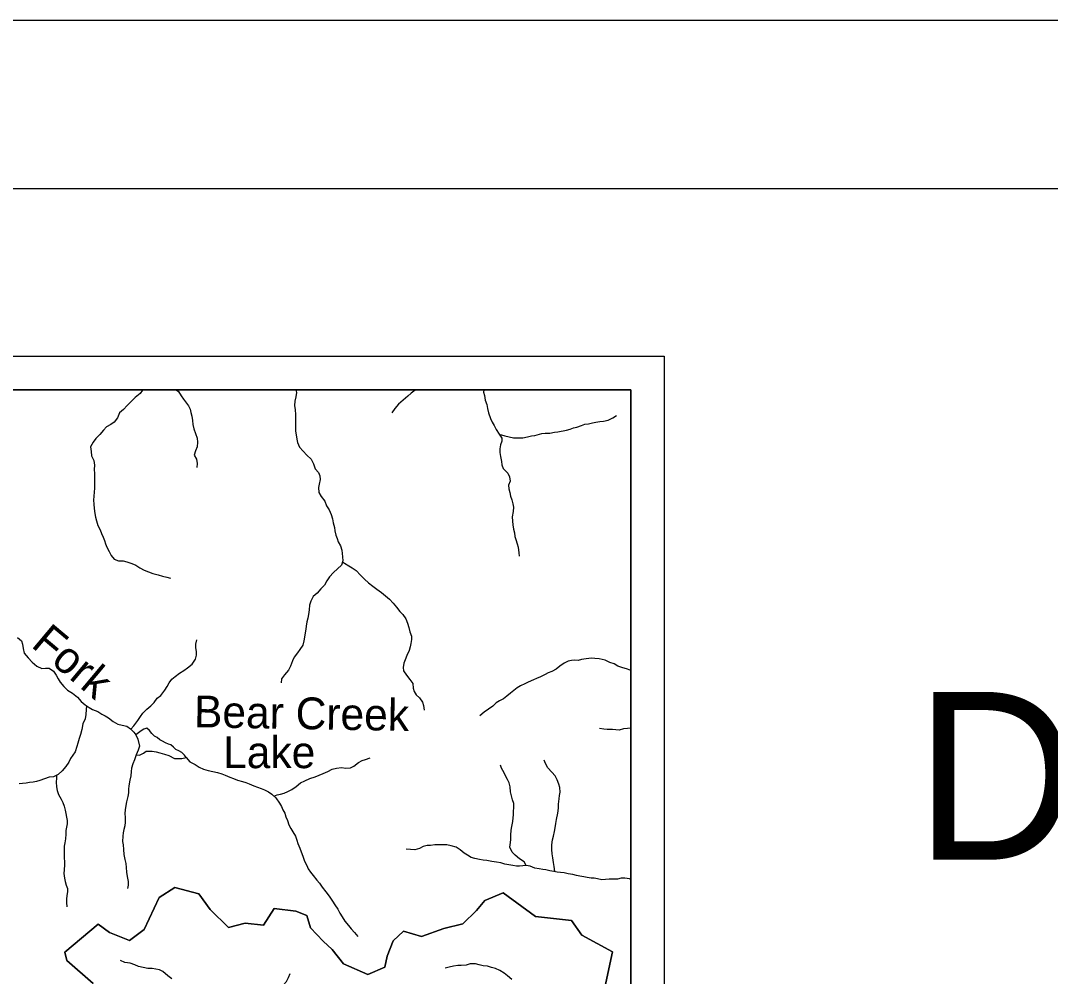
# Model space of a CAD drawing. Extents: x 0 to 34, y 0 to 22.
# Drawn here: x 7.083 to 10.15, y 19.152 to 22 of the extents above; entities that cross this region are included whole.
import ezdxf

# ---------------------------------------------------------------- set-up
doc = ezdxf.new("R2010")
doc.units = 0
for name, color, linetype in [('Default', 7, 'Continuous'), ('GM_X_Minor_Lake', 7, 'Continuous'), ('GM_X_Minor_Lake_Text', 7, 'Continuous'), ('GM_X_Minor_River', 7, 'Continuous'), ('GM_X_Minor_River_Text', 7, 'Continuous'), ('SH_Border', 7, 'Continuous'), ('SH_Cut_Line', 7, 'Continuous'), ('SH_Data', 7, 'Continuous'), ('SH_Text', 7, 'Continuous')]:
    doc.layers.add(name, color=color, linetype=linetype)

msp = doc.modelspace()

# ---------------------------------------------------------------- linework, layer by layer
at = {"layer": 'Default'}
for points in [[(8.9, 18.9397), (8.9, 20.9), (6.416, 20.9), (6.3907, 20.8258), (6.4542, 20.7247), (6.5744, 20.5412), (6.467, 20.1963), (6.4168, 20.1498), (6.3788, 19.8553), (6.4211, 19.7542), (6.3989, 19.6679), (6.4166, 19.6301), (6.1627, 19.4643), (5.935, 19.2098), (5.9881, 19.1818), (6.0158, 19.1833), (6.0473, 19.1917), (6.082, 19.1783), (6.0902, 19.1718), (6.104, 19.1492)], [(8.806, 19.0402), (8.8461, 19.2253), (8.7546, 19.2751), (8.7234, 19.3184), (8.6167, 19.3311), (8.5195, 19.401), (8.4658, 19.3785), (8.4408, 19.3485), (8.3998, 19.3091), (8.3436, 19.295), (8.2763, 19.2712), (8.2227, 19.2867), (8.1921, 19.2586), (8.1741, 19.2129), (8.1672, 19.1796), (8.1166, 19.1578), (8.0447, 19.1898), (8.0103, 19.2328), (7.9834, 19.257), (7.9456, 19.297), (7.9351, 19.3339), (7.9023, 19.3469), (7.8376, 19.3545), (7.8063, 19.3044), (7.7511, 19.3112), (7.7017, 19.2978), (7.6475, 19.3516), (7.6132, 19.398), (7.5418, 19.4167), (7.4956, 19.3869), (7.4506, 19.2922), (7.407, 19.2589), (7.3478, 19.2832), (7.314, 19.3079), (7.2146, 19.2241), (7.2203, 19.1994), (7.299, 19.1308)], [(7.299, 19.1308), (7.2203, 19.1994), (7.2146, 19.2241), (7.314, 19.3079), (7.3478, 19.2832), (7.407, 19.2589), (7.4506, 19.2922), (7.4956, 19.3869), (7.5418, 19.4167), (7.6132, 19.398), (7.6475, 19.3516), (7.7017, 19.2978), (7.7511, 19.3112), (7.8063, 19.3044), (7.8376, 19.3545), (7.9023, 19.3469), (7.9351, 19.3339), (7.9456, 19.297), (7.9834, 19.257), (8.0103, 19.2328), (8.0447, 19.1898), (8.1166, 19.1578), (8.1672, 19.1796), (8.1741, 19.2129), (8.1921, 19.2586), (8.2227, 19.2867), (8.2763, 19.2712), (8.3436, 19.295), (8.3998, 19.3091), (8.4408, 19.3485), (8.4658, 19.3785), (8.5195, 19.401), (8.6167, 19.3311), (8.7234, 19.3184), (8.7546, 19.2751), (8.8461, 19.2253), (8.806, 19.0402)]]:
    msp.add_lwpolyline(points, dxfattribs=at)
at = {"layer": 'GM_X_Minor_Lake'}
for points in [[(7.5761, 19.8042), (7.5709, 19.8118), (7.563, 19.8191), (7.5543, 19.8245), (7.5453, 19.8287), (7.5382, 19.8356), (7.5303, 19.8421), (7.5227, 19.8445), (7.5137, 19.8483), (7.5054, 19.8526), (7.4974, 19.8572), (7.4895, 19.8637), (7.4809, 19.8683), (7.473, 19.876), (7.4666, 19.8844), (7.4584, 19.8913), (7.45, 19.8891), (7.4416, 19.8838), (7.4336, 19.8782), (7.4256, 19.8722)], [(7.4256, 19.8722), (7.4316, 19.8591), (7.4367, 19.8384), (7.4332, 19.8259), (7.4263, 19.8123), (7.4365, 19.8114), (7.449, 19.817), (7.457, 19.823), (7.4748, 19.8229), (7.4865, 19.8209), (7.4971, 19.8178), (7.5107, 19.8142), (7.5239, 19.8103), (7.5413, 19.8011), (7.5496, 19.8018), (7.5629, 19.8013), (7.5761, 19.8042)]]:
    msp.add_lwpolyline(points, dxfattribs=at)
at = {"layer": 'GM_X_Minor_River'}
for points in [[(7.446, 20.9), (7.4452, 20.899), (7.4384, 20.8892), (7.4239, 20.8768), (7.4113, 20.8644), (7.3998, 20.8535), (7.3887, 20.8415), (7.3773, 20.8313), (7.3711, 20.8169), (7.3608, 20.8038), (7.3512, 20.7962), (7.3383, 20.7895), (7.3299, 20.7793), (7.3184, 20.7669), (7.3062, 20.7549), (7.2986, 20.7436)], [(7.5463, 20.9), (7.5527, 20.8947), (7.5606, 20.8818), (7.5673, 20.8719), (7.583, 20.852), (7.5875, 20.8425), (7.5893, 20.8326), (7.5923, 20.8212), (7.5944, 20.8083), (7.5955, 20.7969), (7.5984, 20.7836), (7.6032, 20.7695), (7.6084, 20.7558), (7.6094, 20.7437), (7.6089, 20.7296), (7.6039, 20.7183), (7.5992, 20.7054), (7.6067, 20.6928), (7.6081, 20.6803), (7.6072, 20.6682)], [(7.9019, 20.9), (7.9044, 20.8922), (7.9028, 20.8786), (7.8997, 20.8665), (7.8984, 20.8532), (7.9002, 20.8403), (7.9016, 20.8259), (7.9012, 20.8164), (7.9014, 20.8023), (7.9017, 20.7902), (7.9016, 20.7762), (7.9034, 20.7655)], [(8.2591, 20.9), (8.2574, 20.8988), (8.2459, 20.8898), (8.236, 20.8808), (8.2223, 20.8691), (8.2086, 20.8571), (8.1975, 20.8443), (8.1879, 20.8318)], [(8.4622, 20.9), (8.4618, 20.8929), (8.4643, 20.8827), (8.4665, 20.8686), (8.4713, 20.8564), (8.4731, 20.8439), (8.476, 20.8317), (8.4827, 20.8142), (8.4868, 20.8036), (8.4927, 20.7933), (8.4994, 20.7815), (8.5077, 20.7681), (8.5163, 20.7559), (8.5162, 20.7464), (8.5123, 20.7355), (8.5103, 20.7241), (8.5102, 20.7127), (8.512, 20.7009), (8.5145, 20.6865), (8.5163, 20.6759), (8.52, 20.6652), (8.5343, 20.6511), (8.5391, 20.6408), (8.5406, 20.6279), (8.5359, 20.6158), (8.537, 20.6048), (8.5399, 20.5937), (8.5417, 20.5835), (8.5458, 20.5721), (8.5483, 20.5603), (8.5509, 20.5504), (8.5493, 20.5371), (8.5472, 20.5216), (8.5475, 20.5083), (8.5489, 20.4973), (8.5503, 20.4844), (8.5536, 20.4737), (8.5551, 20.4631), (8.5573, 20.4536), (8.5617, 20.4414), (8.5646, 20.4311), (8.5668, 20.4144), (8.5678, 20.4042)], [(8.5094, 20.7657), (8.5152, 20.7658), (8.5254, 20.7623), (8.5375, 20.7603), (8.5511, 20.7572), (8.5655, 20.7567), (8.5784, 20.7573), (8.592, 20.7598), (8.6042, 20.7632), (8.6144, 20.7642), (8.6356, 20.7694), (8.6451, 20.7704), (8.6591, 20.7711), (8.6728, 20.7736), (8.6823, 20.775), (8.7088, 20.7801), (8.7198, 20.7831), (8.7297, 20.7864), (8.7392, 20.7886), (8.7528, 20.7934), (8.7631, 20.7971), (8.7745, 20.7986), (8.7862, 20.8015), (8.7957, 20.8037), (8.8078, 20.8051), (8.8192, 20.8069), (8.8325, 20.8095), (8.8462, 20.8166), (8.8576, 20.8229)], [(7.2986, 20.7436), (7.2909, 20.73), (7.2923, 20.7159), (7.294, 20.7034), (7.3004, 20.6893), (7.3025, 20.6749), (7.302, 20.6623), (7.3027, 20.6506), (7.3026, 20.6407), (7.3029, 20.6274), (7.3024, 20.618), (7.3023, 20.6073), (7.3018, 20.5948), (7.3001, 20.5713), (7.3008, 20.5592), (7.3014, 20.5466), (7.3036, 20.5318), (7.3061, 20.52), (7.3091, 20.5098), (7.3124, 20.4953), (7.3198, 20.4831), (7.3235, 20.4721), (7.3287, 20.4607), (7.3321, 20.4512), (7.3354, 20.4413), (7.3391, 20.431), (7.3462, 20.4184), (7.3525, 20.4066), (7.3611, 20.3955), (7.374, 20.3905), (7.388, 20.39), (7.3985, 20.3869), (7.4136, 20.3826), (7.4261, 20.3779), (7.4378, 20.3699), (7.451, 20.3626), (7.4634, 20.3571), (7.4766, 20.3525), (7.4921, 20.3482), (7.5049, 20.3447), (7.5182, 20.3415), (7.5291, 20.3391)], [(7.9034, 20.7655), (7.9055, 20.753), (7.9074, 20.7431), (7.9129, 20.7286), (7.9246, 20.7175), (7.9347, 20.7049), (7.9478, 20.6931), (7.9549, 20.6797), (7.9601, 20.6641), (7.9698, 20.6534), (7.9735, 20.6439), (7.975, 20.6329), (7.9714, 20.6189), (7.9702, 20.6087), (7.9708, 20.5942), (7.9776, 20.5817), (7.9884, 20.5679), (7.994, 20.5546), (8.0015, 20.542), (8.0074, 20.5287), (8.0111, 20.515), (8.0132, 20.5032), (8.0173, 20.4892), (8.0187, 20.4793), (8.022, 20.4667), (8.025, 20.4565), (8.0287, 20.4466), (8.035, 20.4348), (8.0391, 20.4218), (8.0401, 20.412), (8.0415, 20.4025), (8.0426, 20.3899), (8.0383, 20.3778), (8.0269, 20.3665), (8.0143, 20.356), (8.0028, 20.3428), (7.9944, 20.3304), (7.9878, 20.3183), (7.9764, 20.3066), (7.9657, 20.2942), (7.9538, 20.2837), (7.9469, 20.2701), (7.9434, 20.2583), (7.9422, 20.2443), (7.9398, 20.2303), (7.9382, 20.2193), (7.9354, 20.2087), (7.9327, 20.1958), (7.9318, 20.1864), (7.9306, 20.1761), (7.9278, 20.1632), (7.9266, 20.1519), (7.9235, 20.139), (7.9139, 20.1262), (7.907, 20.1164), (7.8978, 20.1032), (7.8928, 20.0926), (7.8862, 20.0767), (7.8801, 20.0642), (7.869, 20.0511), (7.8598, 20.0386), (7.8589, 20.0265)], [(8.0417, 20.3876), (8.0474, 20.3838), (8.0599, 20.375), (8.0697, 20.3692), (8.0825, 20.3615), (8.0948, 20.3474), (8.1065, 20.3355), (8.1185, 20.3244), (8.1313, 20.3152), (8.1437, 20.3064), (8.1573, 20.2964), (8.1697, 20.2861), (8.1817, 20.2765), (8.1922, 20.2646), (8.2027, 20.252), (8.2121, 20.2398), (8.2211, 20.2303), (8.2304, 20.2173), (8.2349, 20.2051), (8.2393, 20.1922), (8.2418, 20.1792), (8.2467, 20.1655), (8.2473, 20.1557), (8.2453, 20.1443), (8.243, 20.1341), (8.2402, 20.1227), (8.2329, 20.108), (8.2283, 20.0955), (8.224, 20.0857), (8.2216, 20.0724), (8.2231, 20.0622), (8.2321, 20.05), (8.2418, 20.0366), (8.2504, 20.0248), (8.2514, 20.0111), (8.2547, 20.0008), (8.2607, 19.9913), (8.2705, 19.9825), (8.2798, 19.9691), (8.2824, 19.9592), (8.2849, 19.9459)], [(7.0733, 20.1623), (7.0853, 20.152), (7.0883, 20.1425), (7.0897, 20.1295), (7.0934, 20.1155), (7.1046, 20.1017), (7.1166, 20.0884), (7.1305, 20.0765), (7.146, 20.0699), (7.1566, 20.0702), (7.1679, 20.0701), (7.1807, 20.062), (7.1886, 20.0494), (7.1942, 20.0388), (7.2005, 20.0289), (7.2118, 20.0162), (7.2227, 20.0051), (7.2374, 19.9959), (7.2517, 19.984), (7.2625, 19.9714), (7.2746, 19.9611), (7.287, 19.9534), (7.2972, 19.9473), (7.3126, 19.9411), (7.3247, 19.9334), (7.3345, 19.9287), (7.3447, 19.9226), (7.3582, 19.9118), (7.3721, 19.9041), (7.3854, 19.901), (7.399, 19.8979), (7.4103, 19.8902), (7.4196, 19.8799), (7.4256, 19.8722), (7.4316, 19.8591), (7.4367, 19.8384), (7.4332, 19.8259), (7.4263, 19.8123), (7.4365, 19.8114), (7.449, 19.817), (7.457, 19.823), (7.4748, 19.8229), (7.4865, 19.8209), (7.4971, 19.8178), (7.5107, 19.8142), (7.5239, 19.8103), (7.5413, 19.8011), (7.5496, 19.8018), (7.5629, 19.8013), (7.5761, 19.8042), (7.5862, 19.7916), (7.6025, 19.7831), (7.6145, 19.7754), (7.6277, 19.7696), (7.6413, 19.7657), (7.6553, 19.7622), (7.6689, 19.7598), (7.6821, 19.7559), (7.6923, 19.752), (7.7055, 19.7455), (7.7168, 19.7416), (7.7289, 19.7373), (7.7433, 19.7326), (7.7531, 19.7295), (7.7629, 19.726), (7.7776, 19.7198), (7.7885, 19.7156), (7.7991, 19.7121), (7.8089, 19.7078), (7.8206, 19.7017), (7.8304, 19.6947), (7.8424, 19.6844), (7.854, 19.668), (7.8592, 19.6581)], [(7.4111, 19.8892), (7.4198, 19.8992), (7.4317, 19.915), (7.4393, 19.9264), (7.447, 19.9369), (7.4585, 19.9486), (7.4703, 19.958), (7.4806, 19.9681), (7.4898, 19.981), (7.5001, 19.9896), (7.5123, 20.0047), (7.5192, 20.016), (7.525, 20.0273), (7.5327, 20.0379), (7.5433, 20.0458), (7.5563, 20.0559), (7.5688, 20.0638), (7.5799, 20.0716), (7.5932, 20.0829), (7.604, 20.0969), (7.6067, 20.1094), (7.6064, 20.1188), (7.6042, 20.1318), (7.6047, 20.1416), (7.6078, 20.1545)], [(8.7431, 20.0936), (8.7336, 20.0941), (8.7237, 20.093), (8.7135, 20.0912), (8.7013, 20.0859), (8.6883, 20.0769), (8.6777, 20.0675), (8.6647, 20.0603), (8.6541, 20.0562), (8.6446, 20.0517), (8.6316, 20.0446), (8.6195, 20.0393), (8.61, 20.036), (8.5944, 20.0289), (8.5841, 20.024), (8.5712, 20.0184), (8.5613, 20.0116), (8.5517, 20.0045), (8.5418, 19.9965), (8.5308, 19.9867), (8.5212, 19.9796), (8.509, 19.9736), (8.4995, 19.9676), (8.4888, 19.9574), (8.4759, 19.9483), (8.4629, 19.9397), (8.45, 19.9288)], [(8.9, 20.0633), (8.89, 20.068), (8.873, 20.073), (8.8613, 20.0765), (8.8503, 20.0831), (8.8378, 20.0873), (8.8234, 20.0939), (8.8064, 20.0985), (8.7932, 20.0998), (8.7833, 20.1002), (8.767, 20.0988), (8.7537, 20.0962), (8.7431, 20.0936)], [(7.2791, 19.9583), (7.2782, 19.947), (7.2773, 19.9326), (7.275, 19.9197), (7.2684, 19.9046), (7.2645, 19.8876), (7.2606, 19.8732), (7.2571, 19.8611), (7.2535, 19.8475), (7.2497, 19.8369), (7.2446, 19.8217), (7.2381, 19.8112), (7.2316, 19.801), (7.2266, 19.7908), (7.217, 19.7772), (7.2063, 19.7644), (7.1941, 19.7542), (7.1804, 19.7471), (7.1679, 19.7457), (7.1542, 19.7413), (7.1394, 19.7361), (7.1299, 19.7328), (7.1204, 19.7306), (7.1094, 19.7303), (7.0988, 19.7277), (7.0882, 19.727), (7.0783, 19.7256)], [(8.9, 19.8917), (8.89, 19.8906), (8.8782, 19.8895), (8.8653, 19.8862), (8.8554, 19.8867), (8.8456, 19.8879), (8.8297, 19.8883), (8.8198, 19.8892), (8.8073, 19.8908)], [(7.4263, 19.8123), (7.422, 19.7979), (7.4173, 19.7858), (7.4131, 19.7729), (7.4115, 19.7623), (7.4106, 19.7502), (7.4082, 19.7365), (7.4054, 19.7202), (7.4042, 19.7104), (7.4037, 19.6994), (7.4018, 19.6884), (7.3978, 19.6725), (7.3955, 19.6611), (7.3942, 19.6486), (7.3934, 19.6376), (7.3937, 19.6259), (7.3943, 19.6122), (7.3934, 19.6012), (7.3903, 19.5899), (7.388, 19.58), (7.3867, 19.5698), (7.3862, 19.5542), (7.388, 19.544), (7.3894, 19.5307), (7.3897, 19.5155), (7.3934, 19.5007), (7.3955, 19.4885), (7.3973, 19.4764), (7.398, 19.4631), (7.4001, 19.4502), (7.4034, 19.4353), (7.4033, 19.424), (7.4013, 19.4141)], [(7.8366, 19.6894), (7.8463, 19.6927), (7.8565, 19.6953), (7.8679, 19.6982), (7.8789, 19.7034), (7.89, 19.709), (7.9037, 19.7177), (7.9162, 19.7286), (7.9288, 19.7353), (7.944, 19.7416), (7.9603, 19.7472), (7.9839, 19.7568), (7.9976, 19.7624), (8.0109, 19.7695), (8.0238, 19.7728), (8.0382, 19.775), (8.0518, 19.7726), (8.065, 19.774), (8.0749, 19.7785), (8.0886, 19.7897), (8.0997, 19.7957), (8.1103, 19.7983), (8.1236, 19.8031)], [(8.6736, 19.4643), (8.6722, 19.4795), (8.67, 19.492), (8.6675, 19.5054), (8.6656, 19.5175), (8.6646, 19.5304), (8.6647, 19.5441), (8.6667, 19.5593), (8.6698, 19.5699), (8.6733, 19.584), (8.6749, 19.5953), (8.6772, 19.6082), (8.6792, 19.6196), (8.6828, 19.6382), (8.6848, 19.6538), (8.6852, 19.6652), (8.6865, 19.6811), (8.6877, 19.6914), (8.6896, 19.7008), (8.689, 19.7145), (8.686, 19.7252), (8.6808, 19.7377), (8.6748, 19.7499), (8.665, 19.761), (8.6529, 19.7732), (8.6462, 19.787), (8.6421, 19.7965)], [(8.5889, 19.4825), (8.5824, 19.4934), (8.5685, 19.5026), (8.5553, 19.5129), (8.5466, 19.5228), (8.5403, 19.5369), (8.5419, 19.551), (8.5431, 19.5605), (8.5432, 19.573), (8.5436, 19.5878), (8.5456, 19.5992), (8.5484, 19.614), (8.5496, 19.6242), (8.5504, 19.6337), (8.5512, 19.6436), (8.552, 19.655), (8.5518, 19.6675), (8.548, 19.6786), (8.5447, 19.69), (8.5414, 19.7025), (8.5411, 19.7166), (8.5374, 19.7288), (8.5333, 19.7387), (8.5276, 19.7482), (8.5228, 19.7589), (8.5153, 19.7722), (8.5116, 19.7817)], [(7.189, 19.7516), (7.1894, 19.7429), (7.1889, 19.7311), (7.1892, 19.7171), (7.191, 19.7065), (7.1955, 19.6939), (7.2033, 19.6798), (7.2081, 19.6699), (7.2122, 19.6596), (7.2151, 19.6478), (7.2173, 19.6379), (7.2191, 19.6269), (7.2209, 19.6167), (7.2212, 19.6064), (7.2192, 19.5966), (7.2176, 19.5867), (7.2172, 19.5757), (7.2159, 19.5621), (7.2139, 19.5503), (7.2123, 19.5405), (7.2122, 19.5291), (7.2125, 19.5158), (7.2128, 19.5041), (7.2135, 19.4946), (7.213, 19.4843), (7.2121, 19.4699), (7.2117, 19.4585), (7.213, 19.4445), (7.2149, 19.4346), (7.2186, 19.424), (7.2223, 19.4141), (7.2222, 19.4046), (7.2206, 19.3928), (7.2193, 19.3818), (7.2193, 19.372), (7.2199, 19.3594)], [(7.8592, 19.6581), (7.8633, 19.6482), (7.8693, 19.6383), (7.873, 19.6276), (7.8771, 19.6166), (7.8819, 19.604), (7.8875, 19.593), (7.8934, 19.5831), (7.9009, 19.5697), (7.9053, 19.5579), (7.9083, 19.5477), (7.9139, 19.534), (7.9179, 19.5237), (7.9231, 19.5107), (7.9283, 19.4959), (7.935, 19.4826), (7.9391, 19.4727), (7.9458, 19.4631), (7.9537, 19.4524), (7.9653, 19.4391), (7.9724, 19.4295), (7.9807, 19.4184), (7.9915, 19.4043), (8.0016, 19.391), (8.0114, 19.3765), (8.0188, 19.3658), (8.0274, 19.3524), (8.0334, 19.3406), (8.0405, 19.3296), (8.0483, 19.317), (8.0588, 19.304), (8.0671, 19.294), (8.0776, 19.283), (8.0869, 19.2711)], [(8.9, 19.4412), (8.8965, 19.4427), (8.8824, 19.4447), (8.8718, 19.4444), (8.8604, 19.4414), (8.8358, 19.4416), (8.8244, 19.4413), (8.8142, 19.4398), (8.8013, 19.4433), (8.7911, 19.4453), (8.7816, 19.445), (8.7702, 19.447), (8.7604, 19.4489), (8.7486, 19.4513), (8.7388, 19.4532), (8.727, 19.4556), (8.7134, 19.4576), (8.7013, 19.4603), (8.6911, 19.4619), (8.6812, 19.4631), (8.671, 19.4647), (8.6585, 19.4671), (8.6471, 19.4698), (8.6377, 19.471), (8.627, 19.4722), (8.6142, 19.4746), (8.6006, 19.4803), (8.5881, 19.4827), (8.5786, 19.4816), (8.5691, 19.4809), (8.5592, 19.481), (8.5486, 19.4822), (8.5369, 19.4849), (8.5248, 19.4869), (8.5126, 19.4908), (8.4998, 19.4924), (8.4865, 19.4944), (8.471, 19.4971), (8.4604, 19.4983), (8.4494, 19.5007), (8.4358, 19.503), (8.4248, 19.5069), (8.4142, 19.5131), (8.404, 19.5196), (8.3916, 19.5292), (8.3795, 19.5372), (8.3651, 19.5415), (8.3526, 19.5442), (8.3412, 19.5443), (8.328, 19.544), (8.3166, 19.5437), (8.3037, 19.5426), (8.2938, 19.5423), (8.2817, 19.5394), (8.271, 19.5333), (8.2569, 19.5296), (8.2437, 19.5301), (8.2308, 19.5309)], [(7.5328, 19.1449), (7.5211, 19.1541), (7.5067, 19.1667), (7.4962, 19.1721), (7.4856, 19.1737), (7.4742, 19.1757), (7.4617, 19.1758), (7.448, 19.1785), (7.4337, 19.182), (7.4227, 19.1863), (7.4087, 19.1917), (7.3932, 19.1933), (7.3799, 19.1998)], [(8.5456, 19.1426), (8.5332, 19.1537), (8.523, 19.1614), (8.5101, 19.1698), (8.4973, 19.1756), (8.4855, 19.1791), (8.4731, 19.1822), (8.4602, 19.1838), (8.4488, 19.1866), (8.4371, 19.1897), (8.4219, 19.1894), (8.4094, 19.186), (8.3946, 19.1846), (8.3851, 19.1851), (8.3722, 19.1825), (8.3593, 19.1795), (8.3467, 19.177)], [(7.7325, 18.934), (7.7381, 18.9404), (7.7495, 18.9498), (7.7541, 18.9608), (7.758, 18.9737), (7.7687, 18.9869), (7.7805, 18.9983), (7.7871, 19.0096), (7.7985, 19.0243), (7.8092, 19.0376), (7.8165, 19.0478), (7.828, 19.0606), (7.8357, 19.0761), (7.8384, 19.0879), (7.8465, 19.1023), (7.8598, 19.1163), (7.8652, 19.1272), (7.8748, 19.1374), (7.8801, 19.1484), (7.8859, 19.1609)]]:
    msp.add_lwpolyline(points, dxfattribs=at)
at = {"layer": 'SH_Border'}
msp.add_lwpolyline([(1.5, 21.5), (33.5, 21.5), (33.5, 0.5), (1.5, 0.5)], close=True, dxfattribs=at)
at = {"layer": 'SH_Cut_Line'}
for points in [[(0, 0), (34, 0), (34, 22), (0, 22)], [(2.4352, 14.1), (8.9, 14.1), (8.9, 20.9), (2.4845, 20.9), (2.4809, 20.6393), (2.4757, 20.2566), (2.4573, 18.9074), (2.4581, 18.1825), (2.4581, 18.1772), (2.4586, 17.7785), (2.4545, 17.2795), (2.4313, 15.0183), (2.4372, 14.2719)]]:
    msp.add_lwpolyline(points, close=True, dxfattribs=at)
at = {"layer": 'SH_Data'}
for p, q in [((2, 21), (9, 21)), ((9, 21), (9, 14)), ((2.1, 20.9), (8.9, 20.9)), ((8.9, 20.9), (8.9, 14.1))]:
    msp.add_line(p, q, dxfattribs=at)

# ---------------------------------------------------------------- texts
at = {"layer": 'GM_X_Minor_Lake_Text'}
for s, rotation, p in [('Bear Creek', 359.0017, (7.5985, 19.8946)), ('Lake', 0.0018, (7.6858, 19.7727))]:
    msp.add_text(s, height=0.0947, rotation=rotation, dxfattribs=at).set_placement(p)
at = {"layer": 'GM_X_Minor_River_Text'}
msp.add_text('Fork', height=0.0947, rotation=320.0022, dxfattribs=at).set_placement((7.1108, 20.1363))
at = {"layer": 'SH_Text'}
msp.add_text('DEPARTMENT OF TRANSPORTATION', height=0.5, dxfattribs=at).set_placement((9.7466, 19.5))

doc.saveas('drawing.dxf')
